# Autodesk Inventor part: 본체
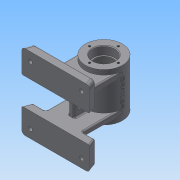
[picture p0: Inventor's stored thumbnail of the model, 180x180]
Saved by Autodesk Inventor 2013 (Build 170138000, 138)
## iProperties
Created: 2016-07
Part Number: 본체
Material: 일반
Document SubType Name: Modeling
Designer: Administrator
Density: 1 g/cm^3
Author: Administrator
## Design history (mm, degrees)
sketch "스케치1"
  geometry: C1 r 27 at (0, 0); 1 further point
  constraints: 1 centre point, 1 coincident
  dimensions: "d0" = 54 diameter of C1
extrude "돌출1" new body sketch "스케치1" stored distance "d1" = 70; taper "d2" = 0 deg
sketch "스케치2"
  geometry: C1 r 16 at (0, 0); 1 further point
  constraints: 1 centre point, 1 coincident
  dimensions: "d3" = 32 diameter of C1
extrude "돌출2" cut sketch "스케치2" distance "d4" = 12; taper "d5" = 0 deg
sketch "스케치3"
  geometry: C1 r 14 at (0, 0); 1 further point
  constraints: 1 centre point, 1 coincident
  dimensions: "d6" = 28 diameter of C1
extrude "돌출3" cut sketch "스케치3" distance "d7" = 2; taper "d8" = 0 deg
sketch "스케치4"
  geometry: C1 r 22 at (0, 0); 1 further point
  constraints: 1 centre point, 1 coincident
  dimensions: "d9" = 44 diameter of C1
extrude "돌출4" cut sketch "스케치4" distance "d10" = 42; taper "d11" = 0 deg
sketch "스케치5"
  geometry: C1 r 16 at (0, 0); 1 further point
  constraints: 1 centre point, 1 coincident
  dimensions: "d12" = 32 diameter of C1
extrude "돌출5" cut sketch "스케치5" distance "d13" = 12; taper "d14" = 0 deg
sketch "스케치6"
  geometry: C1 r 14 at (0, 0); 1 further point
  constraints: 1 centre point, 1 coincident
  dimensions: "d15" = 28 diameter of C1
extrude "돌출6" cut sketch "스케치6" distance "d16" = 2; taper "d17" = 0 deg
chamfer "모따기1" distance "d18" = 1; stored, may be unused: second distance "d19" = 2, angle "d20" = 45 deg
sketch "스케치9"
  geometry: L1 (0, 0)-(0, 21); C1 r 17 at (0, 0) reference; C2 r 27 at (0, 0) reference; 2 further points
  constraints: 2 end point, 1 coincident, 1 vertical
  dimensions: "d23" = 21 distance of L1.start L1.end
hole "구멍1" sketch "스케치9" at (0, 21) diameter "d24" = 3.242; stored, may be unused: countersink angle "d28" = 90 deg, drill point angle "d30" = 118 deg; dims "d25" = 8, "d26" = 4, "d27" = 2, "d29" = 10
node "작업 평면1"
sketch "스케치10"
  geometry: L1 (27, 35)-(-27, 35) reference; C1 r 5 at (0, 13); 1 further point
  constraints: 1 centre point, 1 vertical alignment
  dimensions: "d35" = 10 diameter of C1; "d36" = 22 distance from line of L1 C1.centre
extrude "돌출7" join sketch "스케치10" stored distance "d37" = 2; taper "d38" = 0 deg
hole "구멍2" diameter "d41" = 5.188; stored, may be unused: countersink angle "d45" = 90 deg, drill point angle "d47" = 0 deg; dims "d39" = 10, "d40" = 10, "d42" = 15, "d43" = 4, "d44" = 2, "d46" = 15
fillet "모깎기2" dims "d48" = 3, "d49" = 0.3
node "작업 평면3"
node "작업 평면7"
node "작업 평면8"
sketch "스케치27"
  geometry: L1 (44.96, -58)-(-45.632, -58); L2 (-50, -70)-(49.328, -70); L3 (-51.088, -58.049)-(-45.649, -58.045); L4 (49.328, -70)-(44.96, -58); L5 (-50, -70)-(-45.632, -58); 3 further points
  constraints: 10 end point, 3 point on line, 1 horizontal, 1 parallel, 1 vertical alignment
  dimensions: "d137" = 70 distance from line of L2 point (0, 0); "d138" = 110 deg angle of L2 L5; "d139" = 110 deg angle of L4 L2; "d140" = 12 distance between parallel lines of L2 L1; "d141" = 23.04322 distance from line of L5 point (0, 0); "d142" = 22.41183 distance from line of point (0, 0) L4
extrude "돌출14" join sketch "스케치27" distance "d143" = 35; taper "d144" = 0 deg
sketch "스케치29"
  geometry: L1 (0, 0)-(0, 35) reference; L2 (0, 35)-(90.593, 35) reference; L3 (90.593, 35)-(90.593, 0) reference; L4 (90.593, 0)-(0, 0) reference; L5 (0, 75)-(0, 110) reference; L6 (0, 110)-(90.593, 110) reference; L7 (90.593, 110)-(90.593, 75) reference; L8 (90.593, 75)-(0, 75) reference; L9 (18.632, 83)-(72.632, 83); L10 (72.632, 83)-(72.632, 75); L11 (72.632, 75)-(18.632, 75); L12 (18.632, 75)-(18.632, 83); L13 (18.632, 83)-(72.632, 75); L14 (72.632, 83)-(18.632, 75); L15 (72.632, 35)-(18.632, 35); L16 (18.632, 35)-(18.632, 27); L17 (18.632, 27)-(72.632, 27); L18 (72.632, 27)-(72.632, 35); L19 (72.632, 35)-(18.632, 27); L20 (18.632, 35)-(72.632, 27); 5 further points
  constraints: 24 end point, 6 midpoint, 4 parallel, 2 horizontal, 2 perpendicular, 2 vertical alignment
  dimensions: "d145" = 54 distance of L10.end L11.end; "d146" = 8 distance of L9.end L10.end; "d147" = 35 distance between parallel lines of L6 L11; "d151" = 54 distance of L17.end L16.end; "d152" = 8 distance of L16.end L15.end; "d153" = 35 distance between parallel lines of L4 L15
extrude "돌출15" join sketch "스케치29" stored distance "d154" = 35; taper "d155" = 0 deg
node "작업 평면9"
sketch "스케치30"
  geometry: 2 further points
  constraints: 2 coincident, 1 other
feature "엠보싱2" sketch "스케치30" dims "d0" = 54, "d156" = 0.5, "d157" = 0
sketch "스케치31"
  geometry: L1 (-49.328, -70)-(-44.96, -58) reference; L2 (-44.96, -58)-(-27, -58) reference; L3 (-27, -58)-(-27, 0) reference; L4 (-27.429, 1.971)-(-26.928, 1.971) reference; L5 (-26.951, 1.618)-(-27.452, 1.618) reference; L6 (50, -70)-(-49.328, -70) reference; L7 (45.632, -58)-(50, -70) reference; L8 (27, -58)-(45.632, -58) reference; L9 (27, 0)-(27, -58) reference; L10 (-4, -26.702)-(-4, -48); L11 (-4, -48)-(4, -48); L12 (4, -48)-(4, -26.702); C1 r 21.236 at (0, 0) reference; A1 r 27 centre (0, 0) between (-27, 0) and (27, 0) reference; A2 r 27 centre (0, 0) between (27, 0) and (-26.928, 1.971) reference; A3 r 27.5 centre (0, 0) between (-27.429, 1.971) and (-27.452, 1.618) reference; A4 r 27 centre (0, 0) between (-26.951, 1.618) and (-27, 0) reference; 2 further points
  constraints: 6 end point, 2 parallel, 2 point on circle, 1 midpoint, 1 perpendicular, 1 vertical alignment
  dimensions: "d158" = 8 distance between parallel lines of L12 L10; "d159" = 21 distance edge to line of A1 L11
extrude "돌출16" join sketch "스케치31" stored distance "d160" = 35; taper "d161" = 0 deg
sketch "스케치32"
  geometry: L1 (41, 29.426)-(41, 34.584) reference; L2 (41, 34.584)-(43, 34.584) reference; L3 (43, 34.584)-(43, 32.818) reference; L4 (43.3, 32.508)-(54, 32.508) reference; L5 (55, 31.477)-(55, 21.298) reference; L6 (55, 21.298)-(48, 21.298) reference; L7 (48, 21.298)-(48, -10) reference; L8 (48, -10)-(75, -10) reference; L9 (75, -10)-(75, -22) reference; L10 (75, -22)-(40, -22) reference; L11 (40, -22)-(40, 0) reference; L12 (40, 0)-(0, 0) reference; L13 (0, 21.298)-(0, 0) reference; L14 (40, 21.298)-(0, 21.298) reference; L15 (40, 0)-(40, 21.298) reference; L16 (2, 26.367)-(38, 26.367) reference; L17 (-1, 34.584)-(-1, 29.426) reference; L18 (-3, 34.584)-(-1, 34.584) reference; L19 (-3, 32.818)-(-3, 34.584) reference; L20 (-14, 32.508)-(-3.3, 32.508) reference; L21 (-15, 21.298)-(-15, 31.477) reference; L22 (-8, 21.298)-(-15, 21.298) reference; L23 (-8, -10)-(-8, 21.298) reference; L24 (-35, -10)-(-8, -10) reference; L25 (-35, -22)-(-35, -10) reference; L26 (0, -22)-(-35, -22) reference; L27 (0, 0)-(0, -22) reference; L28 (38, 69.633)-(2, 69.633) reference; L29 (-1, 66.574)-(-1, 61.416) reference; L30 (-1, 61.416)-(-3, 61.416) reference; L31 (-3, 61.416)-(-3, 63.182) reference; L32 (-3.3, 63.492)-(-14, 63.492) reference; L33 (-15, 64.523)-(-15, 74.702) reference; L34 (-15, 74.702)-(4, 74.702) reference; L35 (4, 74.702)-(4, 78) reference; L36 (4, 78)-(10, 78) reference; L37 (10, 78)-(10, 74.702) reference; L38 (10, 74.702)-(55, 74.702) reference; L39 (55, 74.702)-(55, 64.523) reference; L40 (54, 63.492)-(43.3, 63.492) reference; L41 (43, 63.182)-(43, 61.416) reference; L42 (43, 61.416)-(41, 61.416) reference; L43 (41, 61.416)-(41, 66.574) reference; L44 (12, 13.5)-(28, 13.5); L45 (28, 6.5)-(12, 6.5); A1 r 3.5 centre (12, 10) between (12, 13.5) and (12, 6.5); A2 r 3.5 centre (28, 10) between (28, 6.5) and (28, 13.5); 2 further points
  constraints: 4 end point, 4 point on circle, 4 tangent, 2 centre point, 1 midpoint, 1 vertical alignment, 12 other
  dimensions: "d162" = 7 diameter of A1; "d163" = 7 diameter of A2; "d164" = 23 dimension on A2 A1; "d165" = 8 horizontal distance of A1.centre point (20, 48); "d166" = 32 distance from line of L10 A2.centre
extrude "돌출17" cut sketch "스케치32" stored distance "d167" = 35; taper "d168" = 0 deg
node "작업 평면10"
sketch "스케치34"
  geometry: C1 r 6 at (0, 0); 1 further point
  constraints: 1 centre point, 1 coincident
  dimensions: "d171" = 12 diameter of C1
extrude "돌출18" join sketch "스케치34" stored distance "d172" = 0; taper "d173" = 0 deg
hole "구멍6" diameter "d176" = 5.188; stored, may be unused: countersink angle "d180" = 90 deg, drill point angle "d182" = 0 deg; dims "d174" = 10, "d175" = 10, "d177" = 15, "d178" = 10, "d179" = 4, "d181" = 15
sketch "스케치35"
  geometry: L1 (0, 35)-(18.632, 35) reference; L2 (18.632, 35)-(72.632, 35) reference; L3 (72.632, 35)-(90.593, 35) reference; L4 (90.593, 35)-(90.593, 0) reference; L5 (90.593, 0)-(0, 0) reference; L6 (0, 0)-(0, 35) reference; L7 (18.632, 27)-(18.632, 35) reference; L8 (72.632, 27)-(18.632, 27) reference; L9 (72.632, 35)-(72.632, 27) reference; L10 (18.632, 83)-(72.632, 83) reference; L11 (72.632, 83)-(72.632, 75) reference; L12 (72.632, 75)-(18.632, 75) reference; L13 (18.632, 75)-(0, 75) reference; L14 (0, 75)-(0, 110) reference; L15 (0, 110)-(90.593, 110) reference; L16 (90.593, 110)-(90.593, 75) reference; L17 (90.593, 75)-(72.632, 75) reference; L18 (18.632, 75)-(18.632, 83) reference; L19 (0, 35)-(18.632, 35) reference; L20 (18.632, 35)-(72.632, 35) reference; L21 (72.632, 35)-(90.593, 35) reference; L22 (90.593, 35)-(90.593, 0) reference; L23 (90.593, 0)-(0, 0) reference; L24 (0, 0)-(0, 35) reference; L25 (18.632, 27)-(18.632, 35) reference; L26 (72.632, 27)-(18.632, 27) reference; L27 (72.632, 35)-(72.632, 27) reference; L28 (18.632, 83)-(72.632, 83) reference; L29 (72.632, 83)-(72.632, 75) reference; L30 (72.632, 75)-(18.632, 75) reference; L31 (18.632, 75)-(0, 75) reference; L32 (0, 75)-(0, 110) reference; L33 (0, 110)-(90.593, 110) reference; L34 (90.593, 110)-(90.593, 75) reference; L35 (90.593, 75)-(72.632, 75) reference; L36 (18.632, 75)-(18.632, 83) reference; L37 (-4.368, 110)-(-4.368, 75) reference; L38 (94.96, 110)-(94.96, 75) reference; 5 further points
  constraints: 2 vertical alignment
  dimensions: "d183" = 12.5 distance from line of L15 point (8.132, 97.5); "d184" = 12.5 distance from line of L15 point (83.132, 97.5); "d185" = 12.5 distance from line of L5 point (83.132, 12.5); "d186" = 12.5 distance from line of L5 point (8.132, 12.5); "d196" = 75 distance of point (8.132, 97.5) point (83.132, 97.5); "d197" = 75 distance of point (83.132, 12.5) point (8.132, 12.5) (derived); "d198" = 12.5 distance from line of L37 point (8.132, 97.5)
hole "구멍7" sketch "스케치35" at (8.132, 97.5), (83.132, 97.5), (83.132, 12.5), (8.132, 12.5) diameter "d189" = 6; stored, may be unused: countersink angle "d193" = 90 deg, drill point angle "d195" = 0 deg; dims "d190" = 15, "d191" = 10, "d192" = 4, "d194" = 15
fillet "모깎기4" dims "d201" = 2
fillet "모깎기5" dims "d202" = 2
fillet "모깎기6" dims "d203" = 2
fillet "모깎기7" dims "d204" = 2
fillet "모깎기8" dims "d205" = 5, "d206" = 2
node "솔리드1"
pattern_circular "원형 패턴1" dims angle "d32" = 360 deg
mirror "대칭1"
mirror "대칭2"
node "절단 모서리 투영1"
node "절단 모서리 투영15"
node "절단 모서리 투영16"
node "절단 모서리 투영17"
node "절단 모서리 투영19"
node "절단 모서리 투영20"
other parameters: "d133" = 55
